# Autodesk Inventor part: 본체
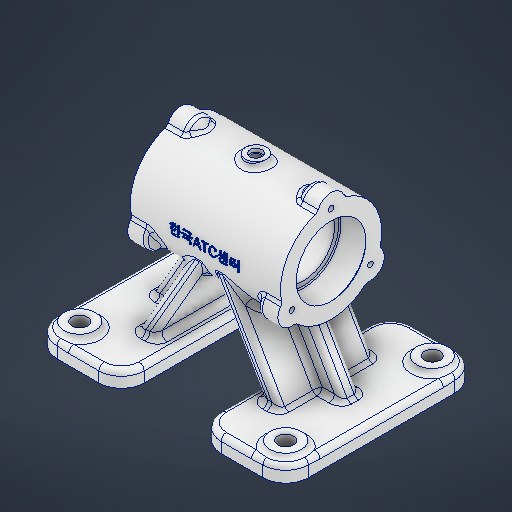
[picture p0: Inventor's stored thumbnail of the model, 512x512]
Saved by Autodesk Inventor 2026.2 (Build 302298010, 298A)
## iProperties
Created: 2026-04
Part Number: 본체
Material: 알루미늄 6061
Document SubType Name: Modeling
Designer: PC2-02
Density: 2.7 g/cm^3
Appearance: 알루미늄 - 평지
Mass: 747.602 g
Surface Area: 677.285 cm^2
Volume: 276.89 cm^3
Author: PC2-02
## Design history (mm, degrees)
sketch "스케치1"
  geometry: L1 (-72, 72)-(72, 72); L2 (-43, 72)-(-43, 101); L3 (-43, 101)-(43, 101); L4 (43, 101)-(43, 72); 3 further points
  constraints: 8 end point, 2 midpoint, 2 point on line, 2 vertical alignment, 1 horizontal, 1 perpendicular, 1 vertical
  dimensions: "d0" = 72 distance from line of point (0, 0) L1; "d1" = 144 distance of L1.start L1.end; "d2" = 86 distance between parallel lines of L4 L2; "d3" = 43 distance from line of point (0, 0) L2 (= 0.5 x d2); "d4" = 58 diameter of L3 L1
revolve "회전1" sketch "스케치1" stored, may be unused: angle "d5" = 90 deg
sketch "스케치2"
  geometry: L1 (72, 55)-(22, 55); L2 (22, 55)-(22, -55); L3 (22, -55)-(72, -55); L4 (72, -55)-(72, 55); L5 (-22, 55)-(-72, 55); L6 (-72, 55)-(-72, -55); L7 (-72, -55)-(-22, -55); L8 (-22, -55)-(-22, 55); 1 further point
  constraints: 16 end point, 4 parallel, 2 horizontal, 2 perpendicular, 2 point on line
  dimensions: "d6" = 144 distance between parallel lines of L6 L4; "d7" = 72 distance from line of point (0, 0) L4 (= 0.5 x d6); "d8" = 110 distance between parallel lines of L3 L1; "d9" = 55 distance from line of point (0, 0) L1 (= 0.5 x d8); "d10" = 44 distance between parallel lines of L8 L2; "d11" = 22 distance from line of point (0, 0) L2 (= 0.5 x d10)
extrude "돌출1" join sketch "스케치2" distance "d12" = 9; taper "d13" = 0 deg
sketch "스케치3"
  geometry: L1 (-43, 43)-(43, 43) reference; L2 (22, 9)-(72, 9) reference; L3 (-72, 9)-(-22, 9) reference; L4 (-22, 9)-(-72, 9) reference; L5 (0, 0)-(0, 43); L6 (22, 0)-(22, 9) reference; L7 (-22, 0)-(-22, 9) reference; L8 (0.006, 64.416)-(32, 9); L9 (0.003, 64.43)-(-32, 9); L10 (9.243, 64.416)-(41.238, 9); L11 (-9.235, 64.43)-(-41.238, 9); L12 (23.1, 64.416)-(55.094, 9); L13 (-23.091, 64.43)-(-55.094, 9); L14 (0.006, 64.416)-(23.1, 64.416); L15 (0.003, 64.43)-(-23.091, 64.43); 4 further points
  constraints: 18 end point, 8 point on line, 5 parallel, 2 midpoint, 1 horizontal
  dimensions: "d24" = 30 deg angle of L5 L9; "d25" = 60 deg angle of L8 L9; "d26" = 8 distance between parallel lines of L8 L10; "d27" = 8 distance between parallel lines of L9 L11; "d28" = 12 distance between parallel lines of L10 L12; "d29" = 12 distance between parallel lines of L11 L13; "d30" = 10 distance from line of L6 L8.end; "d31" = 10 distance from line of L7 L9.end
extrude "돌출2" join sketch "스케치3" stored distance "d32" = 54; taper "d33" = 0 deg
extrude "돌출3" join sketch "스케치3" stored distance "d34" = 10; taper "d35" = 0 deg
sketch "스케치5" dims "d123" = 52
  geometry: C1 r 8 at (0, 26); C2 r 8 at (-22.517, -13); C3 r 8 at (22.517, -13); 9 further points
  constraints: 3 centre point, 1 coincident, 1 vertical alignment, 10 other
  dimensions: "d124" = 16 diameter of C1; "d127" = 360 deg dimension on point (0, 0) C1.centre (derived)
extrude "돌출4" join sketch "스케치5" distance "d47" = 10; taper "d48" = 0 deg
sketch "스케치6"
  geometry: L1 (-43, 101)-(33, 101) reference; L2 (33, 101)-(9.1, 101); L3 (0, 101)-(0, 125.826); L4 (72, 0)-(22, 0) reference; L5 (-43, 43)-(-43, 101) reference; L6 (-43, 72)-(43, 72); L7 (43, 64.75)-(43, 99.942) reference; L8 (43, 106)-(33, 106) reference; L9 (25, 98)-(43, 98); L10 (25, 98)-(33, 106); L11 (33, 106)-(33, 99.942) reference; L12 (33, 106)-(33, 98); 3 further points
  constraints: 12 end point, 5 point on line, 2 horizontal, 2 midpoint, 1 perpendicular, 1 vertical, 1 vertical alignment
  dimensions: "d162" = 72 distance between parallel lines of L4 L6; "d166" = 16 diameter of L8 L9; "d167" = 45 deg angle of L10 L9
revolve "회전3" sketch "스케치6" stored, may be unused: angle "d50" = 360 deg
sketch "스케치8"
  geometry: L1 (-6, 92)-(-6, 104); L2 (-6, 104)-(6, 104); L3 (6, 104)-(6, 92); L4 (6, 92)-(-6, 92); L5 (-6, 52.159)-(6, 52.159); L6 (6, 52.159)-(6, 40); L7 (6, 40)-(-6, 40); L8 (-6, 40)-(-6, 52.159); L9 (-43, 43)-(43, 43) reference; L10 (-28, 101)-(28, 101) reference; L11 (27, 90)-(-27, 90) reference; L12 (0, 90)-(0, 117.313); L13 (0, 52.159)-(0, 27.547); 6 further points
  constraints: 20 end point, 4 midpoint, 4 perpendicular, 3 equal length, 3 vertical, 2 parallel, 1 horizontal
  dimensions: "d65" = 3 distance between parallel lines of L10 L2; "d66" = 12 distance between parallel lines of L3 L1; "d67" = 6 distance from line of point (0, 101) L3 (= 0.5 x d66); "d68" = 12 distance between parallel lines of L6 L8; "d69" = 6 distance from line of point (0, 43) L6 (= 0.5 x d68); "d70" = 3 distance between parallel lines of L9 L7
revolve "회전5" stored, may be unused: angle "d71" = 90 deg
revolve "회전6" stored, may be unused: angle "d72" = 90 deg
fillet "모깎기1" dims "d73" = 13
sketch "스케치9"
  geometry: L1 (72, -42)-(72, 42) reference; L2 (59, 55)-(35, 55) reference; C1 r 9 at (59, 42); C2 r 9 at (-59, 42); C3 r 9 at (-59, -42); C4 r 9 at (59, -42); 1 further point
  constraints: 4 centre point, 3 equal radius, 2 vertical alignment, 1 horizontal alignment
  dimensions: "d74" = 13 distance from line of L1 C1.centre; "d75" = 13 distance from line of C1.centre L2; "d76" = 18 diameter of C1; "d77" = 118 distance of C2.centre C1.centre; "d78" = 84 distance of C3.centre C2.centre; "d79" = 42 vertical distance of point (0, 0) C2.centre (= 0.5 x d78)
extrude "돌출5" join sketch "스케치9" distance "d80" = 3; taper "d81" = 0 deg
sketch "스케치10"
  geometry: C1 r 9 at (0, 0) reference; C2 r 9 at (0, 84) reference; C3 r 9 at (118, 0) reference; C4 r 9 at (118, 84) reference; 5 further points
  constraints: 4 coincident
hole "구멍1" sketch "스케치10" at (0, 0), (0, 84), (118, 0), (118, 84) diameter "d82" = 9; stored, may be unused: countersink angle "d86" = 90 deg, drill point angle "d88" = 118 deg; dims "d83" = 6, "d84" = 17.3, "d85" = 2, "d87" = 8
sketch "스케치13" dims "d104" = 52
  geometry: L1 (-42, -101)-(42, -101) reference; 4 further points
  constraints: 3 vertical alignment, 1 midpoint, 2 other
  dimensions: "d103" = 72 distance from line of L1 point (0, -29)
hole "구멍4" sketch "스케치13" at (0, -3) diameter "d105" = 3.242; stored, may be unused: countersink angle "d109" = 90 deg, drill point angle "d111" = 118 deg; dims "d106" = 8, "d107" = 4, "d108" = 2, "d110" = 10
fillet "모깎기2" dims "d115" = 3
fillet "모깎기3" dims "d116" = 3
fillet "모깎기4" dims "d117" = 3
fillet "모깎기5" dims "d118" = 3
sketch "스케치14"
  geometry: L1 (-54.064, 72)-(70.135, 72); L2 (72, 0)-(59, 0) reference; L3 (-43, 64.75)-(-43, 99.942) reference; L4 (-43, 72)-(-43, 91.952); L5 (-43, 72)-(-43, 92); L6 (-27, 92.4)-(-27, 90); L7 (27, 90)-(27, 92.4); L8 (27.6, 93)-(42, 93); L9 (43, 64.75)-(43, 99.942) reference; L10 (-27.6, 93)-(-42, 93); L11 (-27, 90)-(27, 90); L12 (-42, 93)-(-43, 92); L13 (43, 92)-(43, 72); L14 (42, 93)-(43, 92); A1 r 0.6 centre (-27.6, 92.4) between (-27, 92.4) and (-27.6, 93); A2 r 0.6 centre (27.6, 92.4) between (27.6, 93) and (27, 92.4); 5 further points
  constraints: 22 end point, 11 point on line, 4 point on circle, 4 tangent, 3 horizontal, 2 centre point, 1 equal radius, 1 parallel, 1 perpendicular, 1 vertical
  dimensions: "d131" = 72 distance between parallel lines of L2 L1; "d132" = 42 diameter of L10 L1; "d133" = 16 distance between parallel lines of L3 L6; "d135" = 36 diameter of L11 L1; "d136" = 16 distance between parallel lines of L9 L7; "d137" = 42 diameter of L8 L1; "d138" = 0.6 radius of A1; "d139" = 1 distance of L10.end point (-43, 93); "d140" = 1 distance of L5.end point (-43, 93) (= d139); "d141" = 1 distance of L8.end point (43, 93); "d142" = 1 distance of L13.start point (43, 93) (= d141)
revolve "회전7" sketch "스케치14" stored, may be unused: angle "d143" = 90 deg
sketch "스케치15"
  geometry: C1 r 6 at (0, 0) reference; 2 further points
  constraints: 1 coincident
hole "구멍5" sketch "스케치15" at (0, 0) diameter "d144" = 5.1881; stored, may be unused: countersink angle "d148" = 90 deg, drill point angle "d150" = 118 deg; dims "d145" = 12, "d146" = 7, "d147" = 2, "d149" = 16
sketch "스케치16"
  geometry: C1 r 6 at (0, 0) reference; 2 further points
  constraints: 1 coincident
hole "구멍6" sketch "스케치16" at (0, 0) diameter "d151" = 5.1881; stored, may be unused: countersink angle "d155" = 90 deg, drill point angle "d157" = 118 deg; dims "d152" = 12, "d153" = 7, "d154" = 2, "d156" = 8
fillet "모깎기6" dims "d168" = 3
fillet "모깎기7" dims "d169" = 3
fillet "모깎기9" dims "d171" = 3
fillet "모깎기10" dims "d172" = 3
fillet "모깎기11" dims "d173" = 3
sketch "스케치17" dims "d0" = 72, "d1" = 144, "d2" = 86, "d3" = 43 (= 0.5 x d2), "d4" = 58
  geometry: 2 further points
  constraints: 1 vertical alignment, 1 other
  dimensions: "d174" = 72 distance of point (0, 0) point (0, 72)
feature "엠보싱1" sketch "스케치17" dims "d0" = 72, "d1" = 144, "d2" = 86, "d3" = 43 (= 0.5 x d2), "d4" = 58, "d13" = 0, "d175" = 0.5, "d176" = 0
node "솔리드1"
pattern_circular "원형 패턴1" dims angle "d52" = 360 deg
mirror "미러1"
pattern_circular "원형 패턴2" dims angle "d113" = 360 deg
mirror "미러2"
mirror "미러3"
node "스케치 - 원형 패턴2" dims "d127" = 360 deg (derived)
feature "A9D066F2-1C7D-4E18-AEED-F7BC21143FA4" dims "d105" = 3.242, "d106" = 8, "d107" = 4, "d108" = 2, "d109" = 90 deg, "d110" = 10, "d111" = 118 deg
